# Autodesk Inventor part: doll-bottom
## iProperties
Author: Administrator
Created: 2001-10
Part Number: doll-bottom
Document SubType Name: Modeling
Designer: Administrator
Control State: 0
Master: False
Checked Out: False
PropertySet Name: Design Tracking Control
Shininess: 64.0
Angle Display Precision: 2
Document Length Units: 11272
Document Angle Units: 11286
Document Time Units: 11279
Document Mass Units: 11290
Document Length Units Precision: 3
Document Angle Units Precision: 2
Compacted: True
PropertySet Name: _Private Model Information
Density: 0.0
Volumn: 0.0
Area: 0.0
PropertySet Name: Model Information
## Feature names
1. Revolution1
2. Shell1
3. Split1
4. Extrusion1
